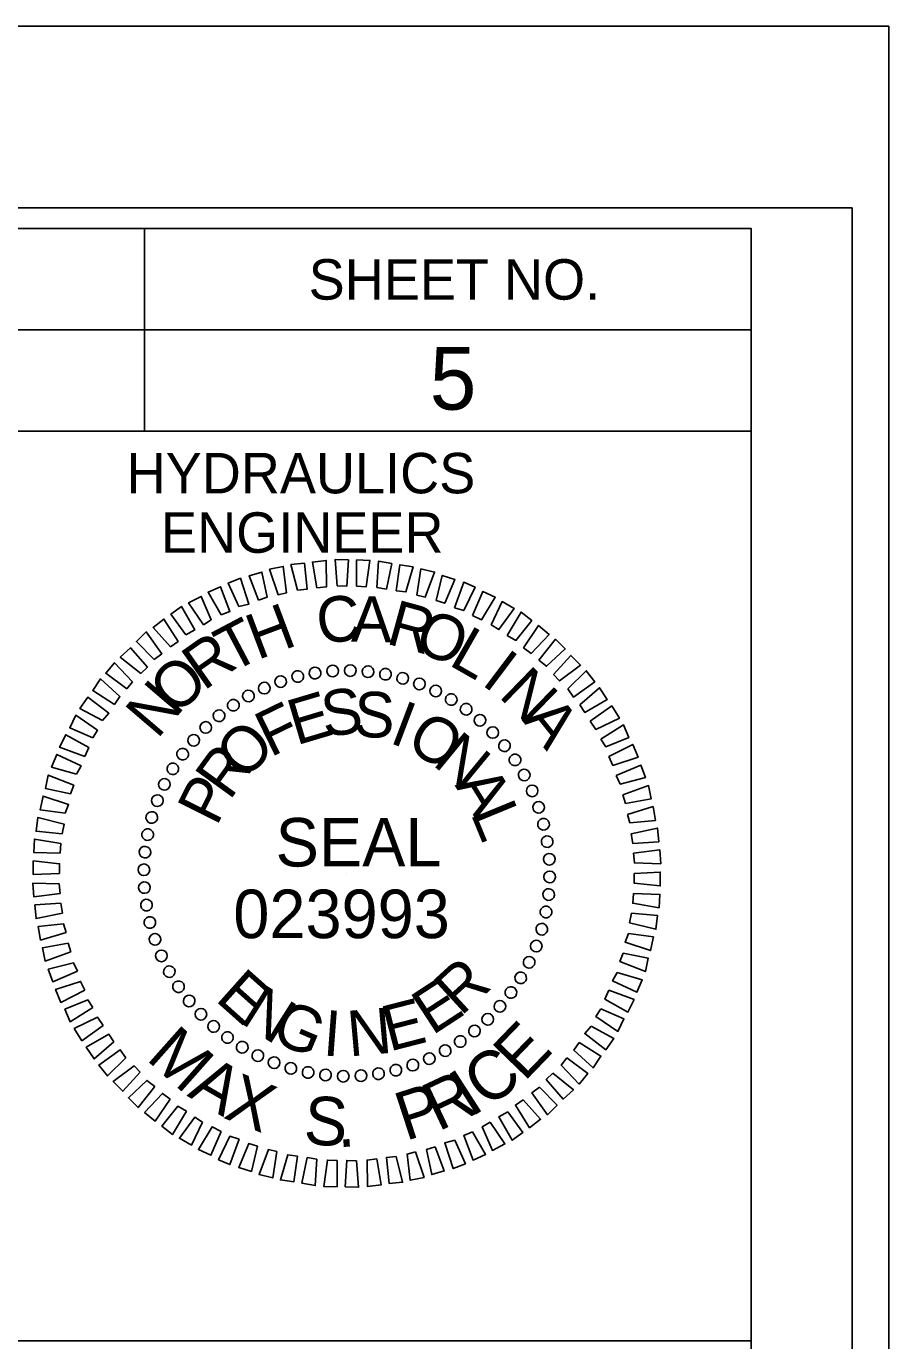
# Model space of a CAD drawing. Extents: x 575424 to 577182, y -52702 to -51602.
# Drawn here: x 577075.6 to 577182.2, y -51765 to -51602.5 of the extents above; entities that cross this region are included whole.
import ezdxf

# ---------------------------------------------------------------- set-up
doc = ezdxf.new("R2010")
doc.units = 0
for name, color, linetype in [('Prop PFL Structure Hydraulic Data Label CELL', 7, 'Continuous'), ('Sheet Cutting Line CELL', 7, 'Continuous'), ('Sheet Data Field CELL', 7, 'Continuous'), ('Sheet PE Seal Cell', 7, 'Continuous'), ('Sheet Plot Border Inside CELL', 7, 'Continuous'), ('Sheet Plot Border Outside CELL', 7, 'Continuous'), ('Sheet Profile CELL', 7, 'Continuous'), ('Typical Detail Wedge2 CELL', 7, 'Continuous')]:
    doc.layers.add(name, color=color, linetype=linetype)

# ---------------------------------------------------------------- blocks, each defined once
blk = doc.blocks.new('MSP')
at = {"layer": 'Sheet PE Seal Cell'}
for p, q in [((50.47, 82.91), (50.47, 82.91)), ((41.82, 81.56), (41.82, 81.56)), ((43.92, 82.16), (43.92, 82.16)), ((46.12, 82.56), (46.12, 82.56)), ((48.27, 82.86), (48.27, 82.86)), ((52.67, 82.76), (52.67, 82.76)), ((54.82, 82.41), (54.82, 82.41)), ((56.92, 81.96), (56.92, 81.96)), ((37.87, 79.76), (37.87, 79.76)), ((39.82, 80.76), (39.82, 80.76)), ((59.02, 81.26), (59.02, 81.26)), ((61.02, 80.36), (61.02, 80.36)), ((35.97, 78.61), (35.97, 78.61)), ((62.97, 79.36), (62.97, 79.36)), ((64.77, 78.11), (64.77, 78.11)), ((34.22, 77.36), (34.22, 77.36)), ((66.52, 76.76), (66.52, 76.76)), ((32.57, 75.86), (32.57, 75.86)), ((68.07, 75.26), (68.07, 75.26)), ((31.07, 74.31), (31.07, 74.31)), ((69.57, 73.61), (69.57, 73.61)), ((29.72, 72.56), (29.72, 72.56)), ((70.82, 71.86), (70.82, 71.86)), ((28.47, 70.76), (28.47, 70.76)), ((71.97, 69.96), (71.97, 69.96)), ((27.47, 68.81), (27.47, 68.81)), ((26.57, 66.81), (26.57, 66.81)), ((72.97, 68.01), (72.97, 68.01)), ((73.77, 66.01), (73.77, 66.01)), ((25.87, 64.71), (25.87, 64.71)), ((74.37, 63.91), (74.37, 63.91)), ((25.42, 62.61), (25.42, 62.61)), ((25.07, 60.46), (25.07, 60.46)), ((74.77, 61.71), (74.77, 61.71)), ((75.07, 59.56), (75.07, 59.56)), ((24.92, 58.26), (24.92, 58.26)), ((50.02, 57.81), (50.02, 57.81)), ((75.12, 57.36), (75.12, 57.36)), ((24.97, 56.06), (24.97, 56.06)), ((25.27, 53.91), (25.27, 53.91)), ((74.97, 55.16), (74.97, 55.16)), ((74.62, 53.01), (74.62, 53.01)), ((25.67, 51.71), (25.67, 51.71)), ((74.17, 50.91), (74.17, 50.91)), ((26.27, 49.61), (26.27, 49.61)), ((73.47, 48.81), (73.47, 48.81)), ((27.07, 47.61), (27.07, 47.61)), ((28.07, 45.66), (28.07, 45.66)), ((72.57, 46.81), (72.57, 46.81)), ((71.57, 44.86), (71.57, 44.86)), ((29.22, 43.76), (29.22, 43.76)), ((70.32, 43.06), (70.32, 43.06)), ((30.47, 42.01), (30.47, 42.01)), ((68.97, 41.31), (68.97, 41.31)), ((31.97, 40.36), (31.97, 40.36)), ((67.47, 39.76), (67.47, 39.76)), ((33.52, 38.86), (33.52, 38.86)), ((35.27, 37.51), (35.27, 37.51)), ((65.82, 38.26), (65.82, 38.26)), ((37.07, 36.26), (37.07, 36.26)), ((62.17, 35.86), (62.17, 35.86)), ((64.07, 37.01), (64.07, 37.01)), ((39.02, 35.26), (39.02, 35.26)), ((41.02, 34.36), (41.02, 34.36)), ((60.22, 34.86), (60.22, 34.86)), ((43.12, 33.66), (43.12, 33.66)), ((45.22, 33.21), (45.22, 33.21)), ((47.37, 32.86), (47.37, 32.86)), ((49.57, 32.71), (49.57, 32.71)), ((51.77, 32.76), (51.77, 32.76)), ((53.92, 33.06), (53.92, 33.06)), ((56.12, 33.46), (56.12, 33.46)), ((58.22, 34.06), (58.22, 34.06))]:
    blk.add_line(p, q, dxfattribs=at)
for points in [[(43.92, 92.81), (43.12, 96.01), (44.77, 96.16), (45.12, 92.96)], [(46.32, 93.11), (45.77, 96.31), (47.47, 96.51), (47.52, 93.26)], [(48.82, 93.36), (48.57, 96.61), (50.22, 96.56), (50.02, 93.31)], [(51.22, 93.31), (51.22, 96.56), (52.87, 96.51), (52.42, 93.26)], [(53.72, 93.16), (53.92, 96.41), (55.57, 96.11), (54.92, 92.96)], [(56.12, 92.76), (56.57, 95.96), (58.22, 95.71), (57.32, 92.61)], [(36.67, 90.81), (35.37, 93.71), (36.87, 94.31), (37.92, 91.11)], [(39.12, 91.61), (37.97, 94.61), (39.52, 95.06), (40.17, 91.96)], [(41.52, 92.26), (40.47, 95.41), (42.17, 95.76), (42.57, 92.51)], [(58.67, 92.21), (59.17, 95.46), (60.87, 95.06), (59.72, 91.96)], [(61.07, 91.56), (61.82, 94.66), (63.37, 94.16), (62.12, 91.21)], [(34.47, 89.76), (32.87, 92.56), (34.42, 93.26), (35.57, 90.21)], [(63.32, 90.66), (64.47, 93.81), (65.87, 93.21), (64.47, 90.31)], [(65.57, 89.71), (66.82, 92.66), (68.37, 91.96), (66.67, 89.16)], [(32.32, 88.56), (30.47, 91.26), (32.02, 92.06), (33.27, 89.16)], [(67.87, 88.56), (69.22, 91.41), (70.72, 90.56), (68.82, 87.96)], [(30.12, 87.31), (28.27, 89.86), (29.57, 90.81), (31.22, 87.91)], [(69.82, 87.21), (71.57, 90.11), (72.87, 89.06), (70.92, 86.61)], [(28.22, 85.81), (26.07, 88.21), (27.42, 89.26), (29.17, 86.46)], [(71.87, 85.71), (73.72, 88.46), (75.02, 87.36), (72.82, 85.01)], [(26.22, 84.26), (24.02, 86.46), (25.22, 87.66), (27.17, 84.96)], [(73.77, 84.16), (75.82, 86.76), (77.02, 85.56), (74.72, 83.41)], [(24.57, 82.51), (22.02, 84.56), (23.27, 85.71), (25.37, 83.31)], [(75.57, 82.41), (77.72, 84.76), (78.92, 83.56), (76.32, 81.61)], [(22.82, 80.61), (20.22, 82.56), (21.32, 83.86), (23.52, 81.51)], [(21.32, 78.71), (18.62, 80.41), (19.57, 81.86), (21.97, 79.66)], [(77.32, 80.61), (79.62, 82.86), (80.67, 81.51), (78.02, 79.61)], [(78.82, 78.66), (81.27, 80.76), (82.22, 79.31), (79.42, 77.71)], [(19.82, 76.71), (17.02, 78.21), (18.02, 79.61), (20.62, 77.61)], [(80.12, 76.61), (82.77, 78.51), (83.72, 77.01), (80.82, 75.61)], [(18.62, 74.56), (15.77, 75.81), (16.52, 77.36), (19.22, 75.51)], [(17.62, 72.26), (14.52, 73.41), (15.27, 74.96), (18.12, 73.36)], [(81.42, 74.41), (84.22, 76.16), (84.87, 74.61), (82.02, 73.46)], [(82.42, 72.26), (85.37, 73.76), (86.02, 72.16), (82.92, 71.16)], [(16.62, 70.06), (13.52, 70.96), (14.17, 72.51), (17.17, 71.11)], [(15.87, 67.66), (12.77, 68.31), (13.12, 69.96), (16.27, 68.71)], [(83.32, 69.91), (86.37, 71.21), (86.92, 69.66), (83.82, 68.86)], [(84.12, 67.51), (87.32, 68.66), (87.62, 67.01), (84.47, 66.46)], [(15.22, 65.26), (12.12, 65.66), (12.47, 67.36), (15.62, 66.31)], [(84.72, 65.11), (87.87, 66.06), (88.17, 64.36), (85.02, 64.06)], [(14.82, 62.71), (11.62, 63.01), (11.82, 64.71), (15.07, 63.91)], [(85.17, 62.71), (88.42, 63.41), (88.57, 61.71), (85.37, 61.51)], [(14.57, 60.31), (11.32, 60.41), (11.42, 62.06), (14.67, 61.51)], [(85.47, 60.31), (88.72, 60.71), (88.82, 59.01), (85.57, 59.11)], [(14.52, 57.81), (11.27, 57.66), (11.27, 59.36), (14.52, 59.01)], [(85.52, 57.81), (88.77, 57.96), (88.77, 56.26), (85.52, 56.61)], [(14.57, 55.31), (11.32, 54.91), (11.22, 56.61), (14.47, 56.51)], [(85.47, 55.31), (88.72, 55.21), (88.62, 53.56), (85.37, 54.11)], [(14.87, 52.91), (11.62, 52.21), (11.47, 53.91), (14.67, 54.11)], [(85.22, 52.91), (88.42, 52.61), (88.22, 50.91), (84.97, 51.71)], [(15.32, 50.51), (12.17, 49.56), (11.87, 51.26), (15.02, 51.56)], [(15.92, 48.11), (12.72, 46.96), (12.42, 48.61), (15.57, 49.16)], [(84.82, 50.36), (87.92, 49.96), (87.57, 48.26), (84.42, 49.31)], [(84.17, 47.96), (87.27, 47.31), (86.92, 45.66), (83.77, 46.91)], [(16.72, 45.71), (13.67, 44.41), (13.12, 45.96), (16.22, 46.76)], [(83.42, 45.56), (86.52, 44.66), (85.87, 43.11), (82.87, 44.51)], [(17.62, 43.36), (14.67, 41.86), (14.02, 43.46), (17.12, 44.46)], [(82.42, 43.36), (85.52, 42.21), (84.77, 40.66), (81.92, 42.26)], [(18.62, 41.21), (15.82, 39.46), (15.17, 41.01), (18.02, 42.16)], [(81.42, 41.06), (84.27, 39.81), (83.52, 38.26), (80.82, 40.11)], [(19.92, 39.01), (17.27, 37.11), (16.32, 38.61), (19.22, 40.01)], [(21.22, 36.96), (18.77, 34.86), (17.82, 36.31), (20.62, 37.91)], [(80.22, 38.91), (83.02, 37.41), (82.02, 36.01), (79.42, 38.01)], [(22.72, 35.01), (20.42, 32.76), (19.37, 34.11), (22.02, 36.01)], [(78.72, 36.91), (81.42, 35.21), (80.47, 33.76), (78.07, 35.96)], [(77.22, 35.01), (79.82, 33.06), (78.72, 31.76), (76.52, 34.11)], [(24.47, 33.21), (22.32, 30.86), (21.12, 32.06), (23.72, 34.01)], [(75.47, 33.11), (78.02, 31.06), (76.77, 29.91), (74.67, 32.31)], [(26.27, 31.46), (24.22, 28.86), (23.02, 30.06), (25.32, 32.21)], [(73.82, 31.36), (76.02, 29.16), (74.82, 27.96), (72.87, 30.66)], [(28.17, 29.91), (26.32, 27.16), (25.02, 28.26), (27.22, 30.61)], [(71.82, 29.81), (73.97, 27.41), (72.62, 26.36), (70.87, 29.16)], [(30.22, 28.41), (28.47, 25.51), (27.17, 26.56), (29.12, 29.01)], [(32.17, 27.06), (30.82, 24.21), (29.32, 25.06), (31.22, 27.66)], [(69.92, 28.31), (71.77, 25.76), (70.47, 24.81), (68.82, 27.71)], [(34.47, 25.91), (33.22, 22.96), (31.67, 23.66), (33.37, 26.46)], [(67.72, 27.06), (69.57, 24.36), (68.02, 23.56), (66.77, 26.46)], [(36.72, 24.96), (35.57, 21.81), (34.17, 22.41), (35.57, 25.31)], [(38.97, 24.06), (38.22, 20.96), (36.67, 21.46), (37.92, 24.41)], [(63.37, 24.81), (64.67, 21.91), (63.17, 21.31), (62.12, 24.51)], [(65.57, 25.86), (67.17, 23.06), (65.62, 22.36), (64.47, 25.41)], [(41.37, 23.41), (40.87, 20.16), (39.17, 20.56), (40.32, 23.66)], [(43.92, 22.86), (43.47, 19.66), (41.82, 19.91), (42.72, 23.01)], [(56.12, 22.81), (56.92, 19.61), (55.27, 19.46), (54.92, 22.66)], [(58.52, 23.36), (59.57, 20.21), (57.87, 19.86), (57.47, 23.11)], [(60.92, 24.01), (62.07, 21.01), (60.52, 20.56), (59.87, 23.66)], [(46.32, 22.46), (46.12, 19.21), (44.47, 19.51), (45.12, 22.66)], [(48.82, 22.31), (48.82, 19.06), (47.17, 19.11), (47.62, 22.36)], [(51.22, 22.26), (51.47, 19.01), (49.82, 19.06), (50.02, 22.31)], [(53.72, 22.51), (54.27, 19.31), (52.57, 19.11), (52.52, 22.36)]]:
    blk.add_lwpolyline(points, close=True, dxfattribs=at)
for centre, major_axis in [((43.95, 82.15), (-0.174, 0.699)), ((46.09, 82.58), (-0.113, 0.711)), ((48.27, 82.83), (-0.05, 0.718)), ((50.45, 82.89), (0.013, 0.72)), ((52.64, 82.75), (0.075, 0.716)), ((54.8, 82.43), (0.137, 0.707)), ((39.82, 80.72), (-0.293, 0.658)), ((41.85, 81.52), (-0.234, 0.681)), ((56.93, 81.92), (0.198, 0.692)), ((59, 81.23), (0.258, 0.672)), ((37.86, 79.75), (-0.349, 0.63)), ((61.01, 80.35), (0.316, 0.647)), ((62.93, 79.31), (0.371, 0.617)), ((34.23, 77.3), (-0.453, 0.56)), ((35.99, 78.6), (-0.403, 0.597)), ((64.76, 78.1), (0.423, 0.582)), ((32.59, 75.85), (-0.5, 0.518)), ((66.47, 76.74), (0.472, 0.543)), ((31.09, 74.26), (-0.543, 0.472)), ((68.06, 75.23), (0.518, 0.5)), ((29.73, 72.55), (-0.582, 0.423)), ((69.51, 73.59), (0.56, 0.453)), ((28.52, 70.73), (-0.617, 0.371)), ((70.81, 71.84), (0.597, 0.403)), ((71.95, 69.97), (0.63, 0.349)), ((27.47, 68.81), (-0.647, 0.316)), ((72.93, 68.01), (0.658, 0.293)), ((26.6, 66.8), (-0.672, 0.258)), ((73.73, 65.98), (0.681, 0.234)), ((25.91, 64.72), (-0.692, 0.198)), ((74.35, 63.88), (0.699, 0.174)), ((25.4, 62.6), (-0.707, 0.137)), ((74.79, 61.73), (0.711, 0.113)), ((25.07, 60.43), (-0.716, 0.075)), ((75.04, 59.56), (0.718, 0.05)), ((24.94, 58.25), (-0.72, 0.013)), ((75.09, 57.37), (0.72, -0.013)), ((25, 56.06), (-0.718, -0.05)), ((74.96, 55.19), (0.716, -0.075)), ((25.25, 53.89), (-0.711, -0.113)), ((74.64, 53.03), (0.707, -0.137)), ((25.68, 51.74), (-0.699, -0.174)), ((26.3, 49.65), (-0.681, -0.234)), ((74.12, 50.9), (0.692, -0.198)), ((73.43, 48.82), (0.672, -0.258)), ((27.1, 47.61), (-0.658, -0.293)), ((72.56, 46.82), (0.647, -0.316)), ((28.08, 45.65), (-0.63, -0.349)), ((71.51, 44.89), (0.617, -0.371)), ((29.22, 43.79), (-0.597, -0.403)), ((70.31, 43.07), (0.582, -0.423)), ((30.53, 42.03), (-0.56, -0.453)), ((31.98, 40.39), (-0.518, -0.5)), ((68.94, 41.36), (0.543, -0.472)), ((33.56, 38.88), (-0.472, -0.543)), ((65.8, 38.32), (0.453, -0.56)), ((67.44, 39.77), (0.5, -0.518)), ((35.27, 37.52), (-0.423, -0.582)), ((64.04, 37.02), (0.403, -0.597)), ((37.1, 36.31), (-0.371, -0.617)), ((39.02, 35.27), (-0.316, -0.647)), ((62.18, 35.88), (0.349, -0.63)), ((41.03, 34.4), (-0.258, -0.672)), ((43.1, 33.7), (-0.198, -0.692)), ((56.08, 33.48), (0.174, -0.699)), ((58.18, 34.1), (0.234, -0.681)), ((60.22, 34.9), (0.293, -0.658)), ((45.23, 33.19), (-0.137, -0.707)), ((47.39, 32.87), (-0.075, -0.716)), ((49.58, 32.73), (-0.013, -0.72)), ((51.77, 32.79), (0.05, -0.718)), ((53.94, 33.04), (0.113, -0.711))]:
    blk.add_ellipse(centre, major_axis=major_axis, ratio=0.999708, dxfattribs=at)
for s, height, rotation, p in [('H', 5.64, 20.6195, (38.97, 84.16)), ('C', 5.64, 6.2199, (46.57, 86.16)), ('A', 5.64, 359.0203, (50.52, 86.46)), ('R', 5.64, 344.6211, (54.72, 86.26)), ('T', 5.64, 27.8198, (35.72, 82.51)), ('O', 5.64, 337.4212, (58.07, 85.51)), ('L', 5.64, 330.2209, (62.47, 83.66)), ('R', 5.64, 35.0205, (32.32, 80.31)), ('I', 5.64, 323.0201, (66.52, 81.26)), ('O', 5.64, 42.2217, (28.87, 77.21)), ('N', 5.64, 315.8189, (68.67, 79.71)), ('N', 5.64, 49.4235, (26.57, 74.31)), ('E', 5.64, 16.6111, (43.77, 73.61)), ('S', 5.64, 7.2556, (47.22, 74.66)), ('S', 5.64, 357.9004, (50.82, 74.71)), ('F', 5.64, 25.967, (40.57, 72.11)), ('I', 5.64, 339.1896, (55.12, 74.01)), ('A', 5.64, 308.6172, (71.62, 76.76)), ('O', 5.64, 329.8335, (57.12, 73.31)), ('O', 5.64, 44.6812, (37.27, 69.16)), ('N', 5.64, 320.4766, (60.47, 71.31)), ('R', 5.64, 54.0396, (35.52, 66.71)), ('P', 5.64, 63.3989, (33.92, 63.51)), ('A', 5.64, 301.7603, (63.32, 68.71)), ('L', 5.64, 292.4008, (65.27, 65.26)), ('SEAL', 5.998, 360, (41.22, 58.66)), ('023993', 5.998, 360, (35.99, 49.8)), ('E', 5.64, 318.2769, (33.62, 42.16)), ('R', 5.64, 42.4814, (64.12, 40.06)), ('N', 5.64, 327.634, (36.62, 39.46)), ('E', 5.64, 33.1241, (60.57, 37.71)), ('E', 5.64, 14.4118, (55.27, 35.76)), ('G', 5.64, 336.9902, (40.42, 37.21)), ('I', 5.64, 355.7012, (46.97, 35.31)), ('N', 5.64, 5.0564, (50.32, 35.16))]:
    blk.add_text(s, height=height, rotation=rotation, dxfattribs=at).set_placement(p)
at = {"layer": 'Typical Detail Wedge2 CELL'}
for s, rotation, p in [('E', 46.0383, (71.94, 31.96)), ('M', 318.378, (25.08, 34.85)), ('C', 36.4646, (67.34, 28.67)), ('A', 329.8972, (30.17, 30.33)), ('X', 338.7296, (34.62, 27.61)), ('R', 25.1925, (61.31, 25.85)), ('I', 32.6661, (65.37, 27.59)), ('P', 18.0895, (57.27, 24.69)), ('S', 356.5489, (44.6, 24.35)), ('.', 3.868, (48.91, 23.93))]:
    blk.add_text(s, height=6, rotation=rotation, dxfattribs=at).set_placement(p)

msp = doc.modelspace()

# ---------------------------------------------------------------- linework, layer by layer
at = {"layer": 'Sheet Cutting Line CELL'}
msp.add_line((577182.21, -51602.49), (575498.21, -51602.49), dxfattribs=at)
at = {"layer": 'Sheet Plot Border Inside CELL'}
msp.add_lwpolyline([(577177.71, -51624.94), (575511.21, -51624.94), (575511.21, -52680.04), (577177.71, -52680.04)], close=True, dxfattribs=at)
at = {"layer": 'Sheet Plot Border Outside CELL'}
msp.add_lwpolyline([(577182.21, -51602.49), (575498.21, -51602.49), (575498.21, -52702.49), (577182.21, -52702.49)], close=True, dxfattribs=at)
at = {"layer": 'Sheet Profile CELL'}
for p, q in [((577090.21, -51627.54), (577090.21, -51652.54)), ((576965.16, -51640.04), (577165.21, -51640.04))]:
    msp.add_line(p, q, dxfattribs=at)
for points in [[(577165.21, -51627.49), (575665.21, -51627.49), (575665.21, -52677.49), (577165.21, -52677.49)], [(576965.16, -51627.49), (577165.21, -51627.49), (577165.21, -51652.54), (576965.16, -51652.54)], [(577065.21, -51652.54), (577165.21, -51652.54), (577165.21, -51765.04), (577065.21, -51765.04)]]:
    msp.add_lwpolyline(points, close=True, dxfattribs=at)

# ---------------------------------------------------------------- block references
at = {"layer": 'Prop PFL Structure Hydraulic Data Label CELL'}
msp.add_blockref('MSP', (577065.21, -51765.04), dxfattribs=at)

# ---------------------------------------------------------------- texts
at = {"layer": 'Sheet Data Field CELL'}
msp.add_text('5', height=7.75, dxfattribs=at).set_placement((577125.48, -51649.89))
at = {"layer": 'Sheet Profile CELL'}
for s, p in [('SHEET NO.', (577110.51, -51636.29)), ('HYDRAULICS', (577088.01, -51660.24)), ('ENGINEER', (577092.26, -51667.59))]:
    msp.add_text(s, height=5, dxfattribs=at).set_placement(p)

doc.saveas('drawing.dxf')
